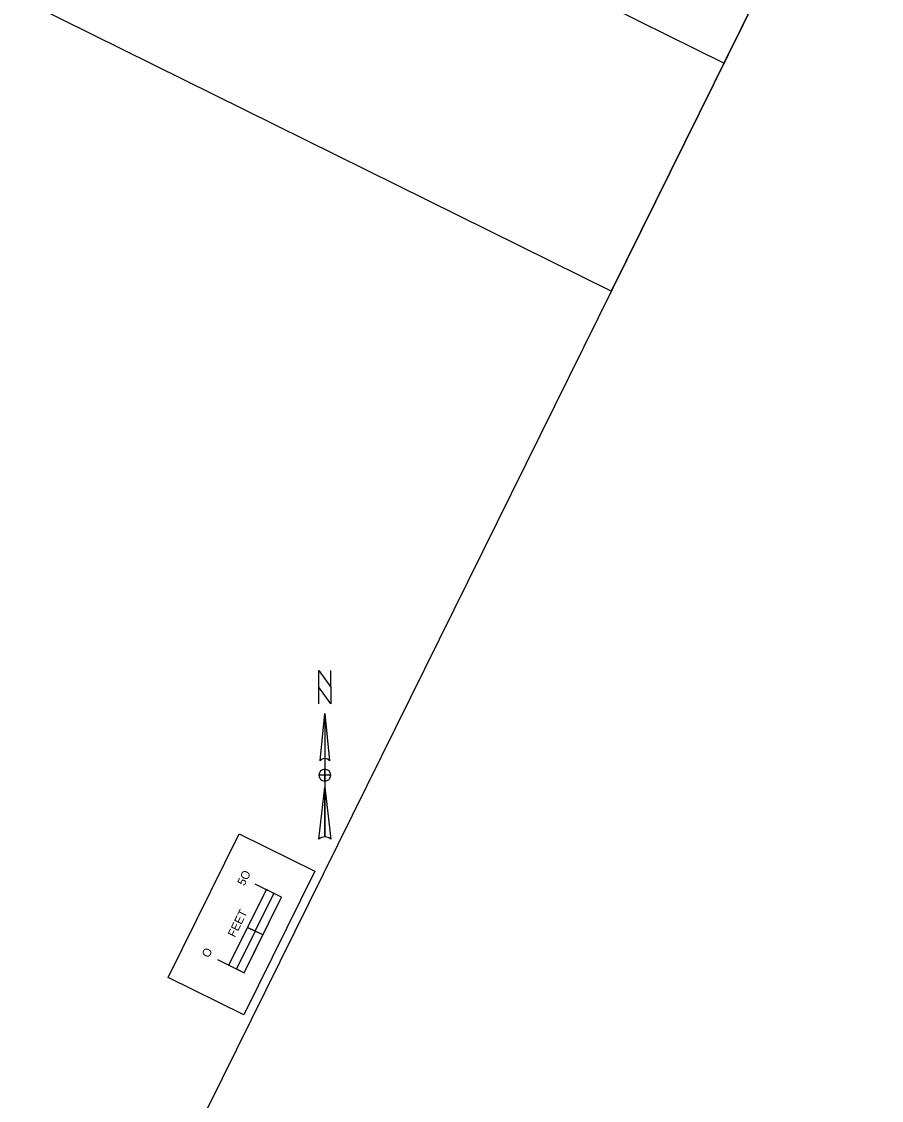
# Model space of a CAD drawing. Extents: x 14104283 to 14128447, y 8633203 to 8671666.
# Drawn here: x 14119187 to 14119697, y 8668018 to 8668657 of the extents above; entities that cross this region are included whole.
import ezdxf

# ---------------------------------------------------------------- set-up
doc = ezdxf.new("R2010")
doc.units = 0
doc.layers.add('dsnNonPlotable', color=7, linetype='Continuous')
doc.layers.add('dsnTextOverlapOdd', color=7, linetype='Continuous')

msp = doc.modelspace()

# ---------------------------------------------------------------- linework, layer by layer
at = {"layer": 'dsnNonPlotable'}
for points in [[(14118631.64, 8668945.1), (14119326.37, 8670350.23), (14120231.75, 8669902.59), (14119537.02, 8668497.46)], [(14118092.03, 8667853.71), (14118786.76, 8669258.84), (14119692.14, 8668811.2), (14118997.41, 8667406.07)]]:
    msp.add_lwpolyline(points, close=True, dxfattribs=at)
at = {"layer": 'dsnTextOverlapOdd'}
for p, q in [((14119367.21, 8668247.06), (14119370.02, 8668218.89)), ((14119367.21, 8668247.06), (14119367.21, 8668173.81)), ((14119364.39, 8668218.89), (14119364.39, 8668218.89)), ((14119364.5, 8668219.15), (14119365.02, 8668219.73)), ((14119367.21, 8668206.91), (14119367.21, 8668206.91)), ((14119363.68, 8668172.4), (14119367.21, 8668203.39)), ((14119330.43, 8668115.73), (14119321.47, 8668120.16)), ((14119330.43, 8668115.73), (14119321.47, 8668120.16))]:
    msp.add_line(p, q, dxfattribs=at)
for points in [[(14119692.14, 8668811.2), (14119603.82, 8668632.57), (14119536.59, 8668665.81), (14119624.91, 8668844.44)], [(14119536.59, 8668665.81), (14119624.91, 8668844.44), (14119692.14, 8668811.2), (14119603.82, 8668632.57)], [(14119370.73, 8668252.69), (14119363.68, 8668262.55), (14119363.68, 8668272.41), (14119370.73, 8668262.55)], [(14119274.42, 8668090.43), (14119316.53, 8668175.59), (14119361.35, 8668153.43), (14119319.24, 8668068.27)], [(14119319.24, 8668068.27), (14119274.42, 8668090.43), (14119316.53, 8668175.59), (14119361.35, 8668153.43)], [(14119325.92, 8668117.96), (14119337, 8668140.37), (14119332.55, 8668142.57), (14119321.47, 8668120.16)], [(14119319.35, 8668093.32), (14119330.43, 8668115.73), (14119325.92, 8668117.96), (14119314.84, 8668095.55)]]:
    msp.add_lwpolyline(points, close=True, dxfattribs=at)
for points in [[(14119363.68, 8668252.69), (14119363.68, 8668272.41), (14119370.73, 8668262.55), (14119370.73, 8668272.41)], [(14119364.39, 8668218.89), (14119367.21, 8668247.06), (14119367.21, 8668220.3)], [(14119370.73, 8668210.44), (14119367.21, 8668210.44), (14119367.21, 8668213.96)], [(14119367.21, 8668206.91), (14119367.21, 8668210.44), (14119363.68, 8668210.44)], [(14119367.21, 8668173.81), (14119367.21, 8668203.39), (14119370.73, 8668172.4)], [(14119303.67, 8668101.07), (14119319.35, 8668093.32), (14119341.51, 8668138.14), (14119325.83, 8668145.89)], [(14119310.39, 8668097.75), (14119332.55, 8668142.57)]]:
    msp.add_lwpolyline(points, dxfattribs=at)
for centre, radius, start, end in [((14119367.21, 8668216.77), 3.52, 90.02039, 143.12574), ((14119367.21, 8668216.78), 3.52, 36.84806, 90.02184), ((14119367.21, 8668210.44), 3.52, 90, 180), ((14119367.21, 8668210.44), 3.52, 0, 90), ((14119367.21, 8668210.44), 3.52, 180, 270), ((14119367.21, 8668210.44), 3.52, 270, 360), ((14119367.21, 8668168.71), 5.1, 89.98939, 133.61895), ((14119367.21, 8668168.71), 5.11, 46.40206, 90.00064)]:
    msp.add_arc(centre, radius, start, end, dxfattribs=at)

# ---------------------------------------------------------------- texts
for s, p in [('5O', (14119319.54, 8668144.46)), ('FEET', (14119313.9, 8668113.89)), ('O', (14119298.46, 8668101.83))]:
    msp.add_text(s, height=5, rotation=63.69117, dxfattribs=at).set_placement(p)

doc.saveas('drawing.dxf')
